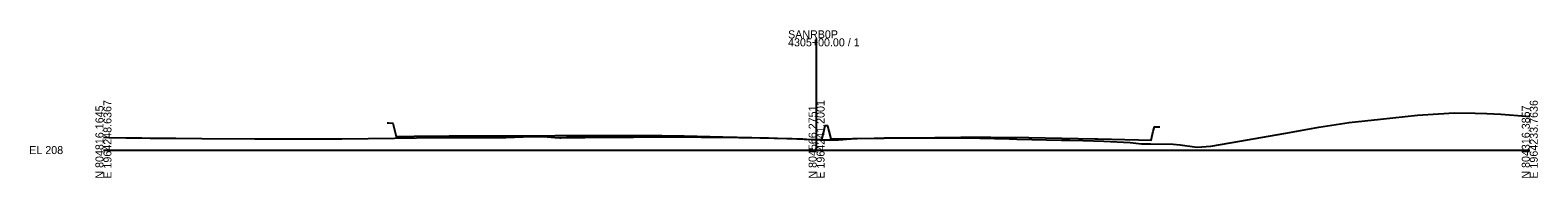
# Model space of a CAD drawing. Extents: x 1995641 to 1997170, y 790368 to 809963.
# Drawn here: x 1996641 to 1997170, y 795868 to 795920 of the extents above; entities that cross this region are included whole.
import ezdxf

# ---------------------------------------------------------------- set-up
doc = ezdxf.new("R2010")
doc.units = 0
for name, color, linetype in [('Default', 7, 'Continuous'), ('RD_GPK_XS_Cell', 7, 'Continuous'), ('RD_Sketch1', 7, 'Continuous'), ('RD_XS_ExGround', 7, 'Continuous'), ('RD_XS_Pave', 7, 'Continuous')]:
    doc.layers.add(name, color=color, linetype=linetype)

msp = doc.modelspace()

# ---------------------------------------------------------------- linework, layer by layer
at = {"layer": 'RD_GPK_XS_Cell'}
for p, q in [((1996917.06, 795878.11), (1996917.06, 795917.19)), ((1996667.06, 795878.11), (1996917.06, 795878.11)), ((1996917.06, 795878.11), (1997167.06, 795878.11))]:
    msp.add_line(p, q, dxfattribs=at)
at = {"layer": 'RD_XS_ExGround'}
msp.add_lwpolyline([(1996667.06, 795882.61), (1996669.02, 795882.56), (1996674.96, 795882.45), (1996680.47, 795882.39), (1996683.46, 795882.31), (1996687.79, 795882.24), (1996692.43, 795882.22), (1996701.55, 795882.18), (1996720.11, 795882.06), (1996731.26, 795882.04), (1996738.94, 795882.04), (1996749.68, 795882.05), (1996750.6, 795882.05), (1996759.82, 795882.18), (1996769.06, 795882.31), (1996776.82, 795882.4), (1996783.92, 795882.48), (1996798.34, 795882.55), (1996808.06, 795882.54), (1996814.18, 795882.7), (1996817.46, 795882.87), (1996818.26, 795882.88), (1996822.57, 795882.75), (1996825.26, 795882.48), (1996827, 795882.45), (1996827.39, 795882.45), (1996829.36, 795882.48), (1996834.14, 795882.5), (1996835.82, 795882.52), (1996842.86, 795882.59), (1996851.06, 795882.64), (1996851.91, 795882.65), (1996852.89, 795882.65), (1996862.41, 795882.69), (1996871.59, 795882.76), (1996876.62, 795882.67), (1996889.83, 795882.51), (1996892.01, 795882.47), (1996907.28, 795882.17), (1996908.52, 795882.13), (1996912.06, 795882.02), (1996912.66, 795881.93), (1996913.5, 795881.92), (1996915.28, 795881.81), (1996917.06, 795881.76), (1996918.23, 795881.73), (1996923.84, 795881.73), (1996924.73, 795881.74), (1996926.29, 795881.78), (1996927.03, 795881.87), (1996927.59, 795881.97), (1996929.14, 795882.04), (1996931.23, 795882.12), (1996940.75, 795882.28), (1996949.57, 795882.4), (1996962.79, 795882.37), (1996969.12, 795882.36), (1996984.51, 795882.01), (1996987.26, 795881.97), (1997002.91, 795881.62), (1997005.78, 795881.57), (1997010.38, 795881.44), (1997014.11, 795881.36), (1997017.75, 795881.26), (1997027, 795880.74), (1997030.9, 795880.27), (1997034.12, 795880.31), (1997042, 795880.16), (1997044.53, 795879.97), (1997049.5, 795879.22), (1997050.44, 795879.09), (1997055.26, 795879.52), (1997061.99, 795880.61), (1997081.58, 795884.08), (1997093.11, 795886.11), (1997103.8, 795887.72), (1997114.75, 795888.92), (1997127.65, 795890.36), (1997135.06, 795890.8), (1997140.57, 795891.14), (1997147.96, 795891.05), (1997152.02, 795890.94), (1997156.97, 795890.72), (1997159.94, 795890.46), (1997162.93, 795890.18), (1997167.06, 795889.82)], dxfattribs=at)
at = {"layer": 'RD_XS_Pave'}
msp.add_lwpolyline([(1996766.54, 795887.61), (1996766.93, 795887.6), (1996768.48, 795887.58), (1996769.64, 795882.89), (1996775.96, 795882.96), (1996788.23, 795883.09), (1996818.99, 795883.13), (1996823.08, 795883.15), (1996825.43, 795883.16), (1996846.85, 795883.2), (1996862.83, 795883.23), (1996870.61, 795883.05), (1996884.19, 795882.72), (1996894.38, 795882.52), (1996900.22, 795882.4), (1996906.66, 795882.19), (1996917.06, 795881.85), (1996918.92, 795881.79), (1996919.45, 795884.06), (1996920.08, 795886.72), (1996920.52, 795886.72), (1996920.86, 795886.72), (1996921.37, 795884.7), (1996922.03, 795882.04), (1996937.24, 795882.31), (1996940.73, 795882.38), (1996943.89, 795882.39), (1996949.39, 795882.42), (1996967.65, 795882.59), (1996978.12, 795882.68), (1996991.41, 795882.46), (1997014.6, 795882.07), (1997015.18, 795882.06), (1997015.51, 795882.06), (1997015.59, 795882.06), (1997029.9, 795881.69), (1997034.29, 795881.57), (1997035.09, 795884.77), (1997035.46, 795886.24), (1997036.74, 795886.24), (1997037.4, 795886.24)], dxfattribs=at)

# ---------------------------------------------------------------- texts
at = {"layer": 'Default'}
msp.add_text('-', height=0.0001, dxfattribs=at).set_placement((1996667.06, 795878.11))
msp.add_text('-', height=0.0001, dxfattribs=at).set_placement((1996667.06, 795878.11))
at = {"layer": 'RD_GPK_XS_Cell'}
for s, p in [('4305+00.00 / 1', (1996907.06, 795914.39)), ('SANRB0P', (1996907.06, 795917.19)), ('EL 208', (1996641.06, 795876.71))]:
    msp.add_text(s, height=2.8, dxfattribs=at).set_placement(p)
for s, p in [('N 804816.1645', (1996667.06, 795868.11)), ('E 1964248.6367', (1996669.86, 795868.11)), ('N 804566.2751', (1996917.06, 795868.11)), ('E 1964241.2001', (1996919.86, 795868.11)), ('N 804316.3857', (1997167.06, 795868.11)), ('E 1964233.7636', (1997169.86, 795868.11))]:
    msp.add_text(s, height=2.8, rotation=90, dxfattribs=at).set_placement(p)
at = {"layer": 'RD_Sketch1'}
for s, p in [('211.74', (1996916.85, 795881.75)), ('211.65', (1996916.85, 795881.66))]:
    msp.add_text(s, height=0.1, dxfattribs=at).set_placement(p)

doc.saveas('drawing.dxf')
